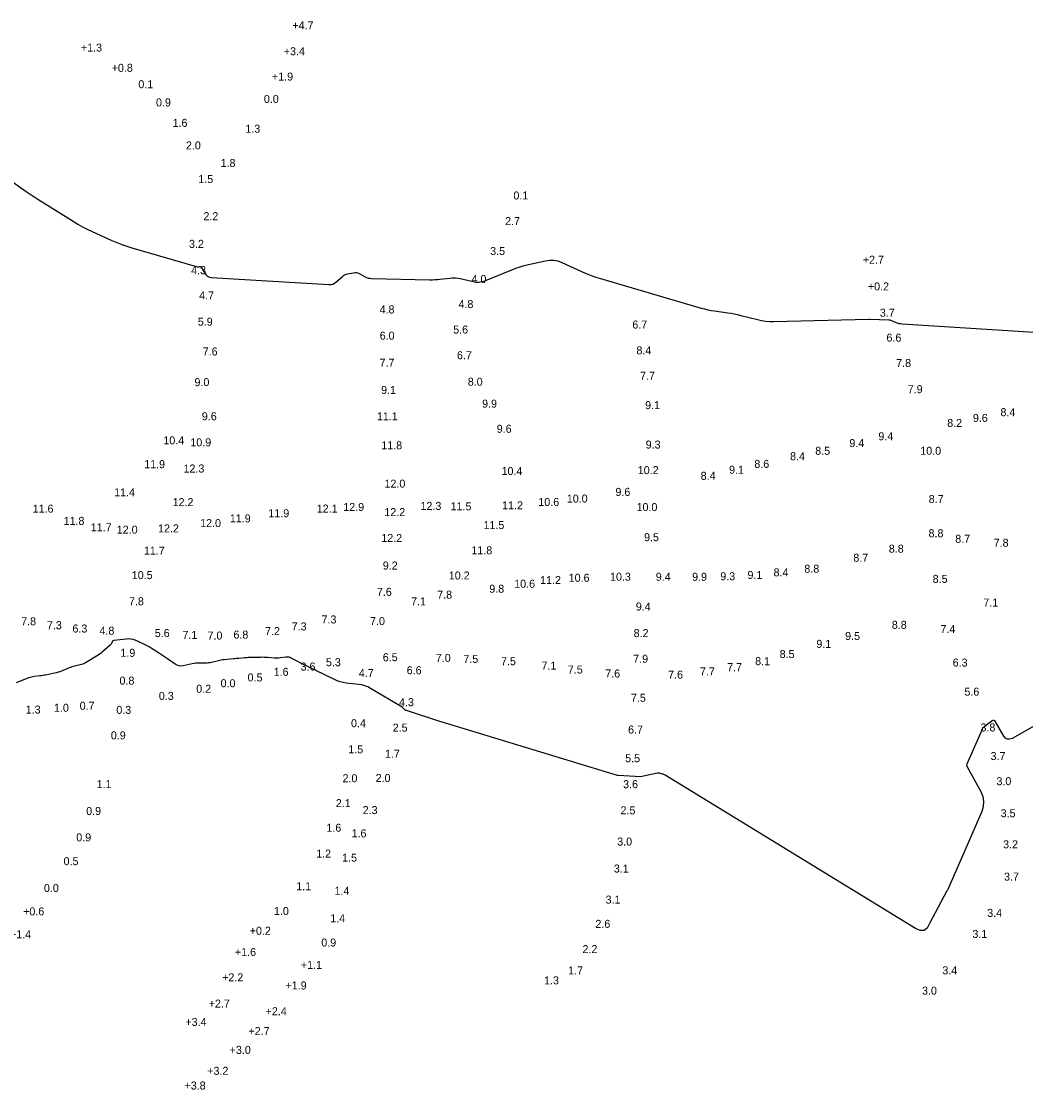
# Model space of a CAD drawing. Extents: x 837127 to 848654, y 3074248 to 3079868.
# Drawn here: x 846091.6 to 846483.6, y 3078129.4 to 3078546.3 of the extents above; entities that cross this region are included whole.
import ezdxf

# ---------------------------------------------------------------- set-up
doc = ezdxf.new("R2010")
doc.units = 0
for name, color, linetype in [('V-HYDS-MAJR', 7, 'Continuous'), ('V-HYDS-SOUN', 7, 'Continuous'), ('V-HYDS-SOUN-EXSS', 7, 'Continuous')]:
    doc.layers.add(name, color=color, linetype=linetype)

msp = doc.modelspace()

# ---------------------------------------------------------------- linework, layer by layer
at = {"layer": 'V-HYDS-MAJR'}
for points in [[(846087.17, 3078484.38), (846093.5, 3078479.9), (846094.61, 3078479.12), (846095.73, 3078478.36), (846096.87, 3078477.62), (846098.01, 3078476.89), (846111.79, 3078468.25), (846113.59, 3078467.17), (846115.42, 3078466.14), (846117.29, 3078465.18), (846119.19, 3078464.28), (846126.85, 3078460.82), (846128.78, 3078459.99), (846130.74, 3078459.22), (846132.72, 3078458.53), (846134.73, 3078457.91), (846160.32, 3078450.48), (846160.43, 3078450.46), (846160.55, 3078450.45), (846160.66, 3078450.45), (846160.77, 3078450.47), (846161.23, 3078450.57), (846161.34, 3078450.58), (846161.44, 3078450.56), (846161.52, 3078450.51), (846161.59, 3078450.43), (846163.63, 3078447.47), (846164.03, 3078447.01), (846164.49, 3078446.67), (846165.03, 3078446.45), (846165.63, 3078446.35), (846211.64, 3078443.58), (846212.39, 3078443.61), (846213.08, 3078443.77), (846213.73, 3078444.07), (846214.33, 3078444.5), (846216.91, 3078446.77), (846217.36, 3078447.12), (846217.85, 3078447.4), (846218.37, 3078447.61), (846218.93, 3078447.76), (846221.22, 3078448.2), (846221.78, 3078448.26), (846222.33, 3078448.22), (846222.87, 3078448.09), (846223.39, 3078447.87), (846225.76, 3078446.59), (846226.34, 3078446.33), (846226.93, 3078446.13), (846227.55, 3078446.01), (846228.18, 3078445.96), (846251.01, 3078445.47), (846252, 3078445.46), (846252.99, 3078445.49), (846253.98, 3078445.55), (846254.97, 3078445.65), (846258.93, 3078446.1), (846259.91, 3078446.17), (846260.9, 3078446.16), (846261.87, 3078446.06), (846262.85, 3078445.88), (846267.88, 3078444.72), (846269.04, 3078444.55), (846270.18, 3078444.55), (846271.31, 3078444.72), (846272.42, 3078445.08), (846283.02, 3078449.34), (846284.61, 3078449.95), (846286.22, 3078450.49), (846287.85, 3078450.96), (846289.5, 3078451.37), (846296.13, 3078452.89), (846297.78, 3078453.13), (846299.4, 3078453.1), (846300.98, 3078452.8), (846302.54, 3078452.22), (846310.26, 3078448.66), (846312.08, 3078447.87), (846313.92, 3078447.14), (846315.78, 3078446.48), (846317.68, 3078445.89), (846356.98, 3078434.4), (846358.24, 3078434.05), (846359.51, 3078433.75), (846360.8, 3078433.5), (846362.09, 3078433.3), (846367.28, 3078432.58), (846368.57, 3078432.38), (846369.86, 3078432.14), (846371.14, 3078431.87), (846372.41, 3078431.56), (846378.97, 3078429.88), (846380.49, 3078429.54), (846382.03, 3078429.31), (846383.57, 3078429.19), (846385.13, 3078429.17), (846422.36, 3078430.06), (846422.93, 3078430.03), (846430.22, 3078429.83), (846430.56, 3078429.75), (846433.09, 3078428.75), (846433.63, 3078428.56), (846434.19, 3078428.42), (846434.75, 3078428.32), (846435.32, 3078428.26), (846495.09, 3078424.46)], [(846542.85, 3078303.14), (846478.27, 3078266.46), (846477.31, 3078266.09), (846476.45, 3078266.11), (846475.71, 3078266.52), (846475.07, 3078267.33), (846471.69, 3078273.14), (846471.62, 3078273.24), (846471.53, 3078273.31), (846471.42, 3078273.35), (846471.3, 3078273.37), (846470.77, 3078273.37), (846470.65, 3078273.35), (846470.53, 3078273.32), (846470.43, 3078273.25), (846470.34, 3078273.17), (846466.6, 3078270.29), (846466.55, 3078270.15), (846466.57, 3078269.96), (846460.43, 3078256.18), (846460.76, 3078255.31), (846466.04, 3078245.71), (846466.85, 3078243.79), (846467.18, 3078241.84), (846467.04, 3078239.87), (846466.41, 3078237.88), (846453.23, 3078207.44), (846453.06, 3078207.16), (846452.83, 3078207), (846446, 3078194.25), (846445.14, 3078192.43), (846443.96, 3078191.49), (846442.45, 3078191.42), (846440.61, 3078192.21), (846342.82, 3078252.13), (846342.6, 3078252.26), (846342.37, 3078252.37), (846342.13, 3078252.46), (846341.88, 3078252.53), (846340.89, 3078252.8), (846340.64, 3078252.85), (846340.39, 3078252.87), (846340.14, 3078252.86), (846339.89, 3078252.82), (846334.44, 3078251.69), (846333.9, 3078251.56), (846333.39, 3078251.38), (846324.5, 3078251.98), (846324.35, 3078251.99), (846324.2, 3078252.02), (846255.41, 3078272.89), (846254.92, 3078273.08), (846241.87, 3078277.34), (846241.7, 3078277.37), (846241.54, 3078277.42), (846241.39, 3078277.5), (846241.25, 3078277.61), (846240.74, 3078278.12), (846240.6, 3078278.25), (846240.46, 3078278.36), (846240.32, 3078278.47), (846240.17, 3078278.57), (846227.83, 3078285.95), (846226.75, 3078286.52), (846225.64, 3078286.96), (846224.48, 3078287.29), (846223.29, 3078287.48), (846218.41, 3078288.03), (846217.21, 3078288.22), (846216.03, 3078288.51), (846214.89, 3078288.9), (846213.78, 3078289.39), (846206.49, 3078292.98), (846206.15, 3078293.15), (846205.82, 3078293.31), (846205.48, 3078293.47), (846205.14, 3078293.64), (846203.79, 3078294.28), (846203.45, 3078294.44), (846203.12, 3078294.61), (846202.78, 3078294.78), (846202.45, 3078294.95), (846196.94, 3078297.81), (846196.44, 3078298.03), (846195.92, 3078298.16), (846195.39, 3078298.2), (846194.85, 3078298.16), (846192.64, 3078297.84), (846192.09, 3078297.77), (846191.54, 3078297.74), (846190.98, 3078297.73), (846190.43, 3078297.77), (846187.66, 3078298), (846187.01, 3078298.05), (846186.36, 3078298.07), (846185.71, 3078298.09), (846185.06, 3078298.08), (846180.83, 3078297.98), (846180.28, 3078297.97), (846179.74, 3078297.94), (846179.2, 3078297.91), (846178.66, 3078297.86), (846176.5, 3078297.67), (846175.96, 3078297.62), (846175.42, 3078297.57), (846174.88, 3078297.53), (846174.34, 3078297.48), (846170.69, 3078297.15), (846170.13, 3078297.08), (846169.58, 3078297), (846169.03, 3078296.88), (846168.48, 3078296.75), (846166.31, 3078296.15), (846165.76, 3078296.02), (846165.21, 3078295.93), (846164.65, 3078295.87), (846164.09, 3078295.85), (846161.03, 3078295.84), (846160.34, 3078295.82), (846159.65, 3078295.77), (846158.96, 3078295.67), (846158.27, 3078295.55), (846154.68, 3078294.78), (846153.87, 3078294.69), (846153.09, 3078294.76), (846152.35, 3078294.99), (846151.64, 3078295.39), (846148.54, 3078297.54), (846147.79, 3078298.06), (846147.03, 3078298.57), (846146.28, 3078299.07), (846145.52, 3078299.57), (846142.23, 3078301.7), (846141.49, 3078302.16), (846140.73, 3078302.59), (846139.95, 3078302.98), (846139.16, 3078303.35), (846135.95, 3078304.74), (846135.14, 3078305.04), (846134.31, 3078305.21), (846133.47, 3078305.28), (846132.61, 3078305.22), (846127.65, 3078304.6), (846127.46, 3078304.56), (846127.3, 3078304.47), (846127.17, 3078304.34), (846127.07, 3078304.17), (846126.73, 3078303.42), (846126.63, 3078303.23), (846126.52, 3078303.07), (846126.39, 3078302.91), (846126.24, 3078302.77), (846123.23, 3078300.21), (846122.66, 3078299.75), (846122.08, 3078299.31), (846121.48, 3078298.9), (846120.86, 3078298.52), (846116.54, 3078295.95), (846116.05, 3078295.69), (846115.56, 3078295.46), (846115.04, 3078295.28), (846114.52, 3078295.13), (846112.37, 3078294.61), (846111.84, 3078294.47), (846111.31, 3078294.31), (846110.79, 3078294.13), (846110.28, 3078293.94), (846107.25, 3078292.72), (846106.58, 3078292.47), (846105.89, 3078292.25), (846105.19, 3078292.05), (846104.48, 3078291.89), (846101.01, 3078291.18), (846100.46, 3078291.07), (846099.91, 3078290.98), (846099.35, 3078290.9), (846098.8, 3078290.83), (846096.57, 3078290.58), (846096.02, 3078290.5), (846095.48, 3078290.38), (846094.94, 3078290.23), (846094.41, 3078290.05), (846089.56, 3078288.18)]]:
    msp.add_lwpolyline(points, dxfattribs=at)

# ---------------------------------------------------------------- texts
at = {"layer": 'V-HYDS-SOUN'}
for s, p in [('+4.7 ', (846197.33, 3078543.17)), ('+1.3 ', (846114.8, 3078534.49)), ('+3.4 ', (846193.99, 3078533.07)), ('+0.8 ', (846126.81, 3078526.6)), ('+1.9 ', (846189.38, 3078523.18)), ('0.1', (846137.22, 3078520.2)), (' 0.0', (846185.07, 3078514.47)), ('0.9', (846144.12, 3078513.1)), ('1.6', (846150.58, 3078505.11)), ('1.3', (846179, 3078502.84)), ('2.0', (846155.79, 3078496.31)), ('1.8', (846169.32, 3078489.46)), ('1.5', (846160.63, 3078483.19)), ('0.1', (846283.63, 3078476.78)), ('2.2', (846162.63, 3078468.7)), ('2.7', (846280.38, 3078466.77)), ('3.2', (846157, 3078457.9)), ('3.5', (846274.56, 3078455.1)), ('+2.7 ', (846420.02, 3078451.7)), ('4.3', (846157.85, 3078447.61)), ('4.0', (846267.28, 3078444.19)), ('+0.2 ', (846422, 3078441.28)), ('4.7', (846160.96, 3078437.76)), ('4.8', (846231.4, 3078432.29)), ('4.8', (846262.19, 3078434.38)), ('3.7', (846426.66, 3078431.03)), ('5.9', (846160.43, 3078427.53)), ('5.6', (846260.13, 3078424.45)), ('6.7', (846330.05, 3078426.39)), ('6.0', (846231.44, 3078422.07)), ('6.6', (846429.25, 3078421.3)), ('7.6', (846162.34, 3078415.89)), ('6.7', (846261.59, 3078414.42)), ('8.4', (846331.65, 3078416.33)), ('7.7', (846231.39, 3078411.53)), ('7.8', (846433.05, 3078411.39)), ('7.7', (846333.06, 3078406.4)), ('9.0', (846159.14, 3078403.92)), ('8.0', (846265.82, 3078404.09)), ('9.1', (846231.98, 3078400.88)), ('7.9', (846437.56, 3078401.18)), ('9.9', (846271.41, 3078395.52)), ('9.1', (846335.05, 3078394.96)), ('9.6', (846162.01, 3078390.6)), ('11.1 ', (846230.34, 3078390.61)), ('9.6', (846462.98, 3078389.95)), ('8.4', (846473.74, 3078392.2)), ('9.6', (846277.12, 3078385.72)), ('8.2', (846452.97, 3078388)), ('10.4 ', (846146.99, 3078381.21)), ('9.4', (846426.09, 3078382.8)), ('10.9 ', (846157.53, 3078380.43)), ('11.8 ', (846232.07, 3078379.26)), ('9.3', (846335.26, 3078379.56)), ('8.5', (846401.44, 3078377.13)), ('9.4', (846414.76, 3078380.14)), ('10.0 ', (846442.44, 3078377.13)), ('8.4', (846391.62, 3078375)), ('11.9 ', (846139.51, 3078371.91)), ('12.3 ', (846154.86, 3078370.21)), ('10.4 ', (846278.99, 3078369.24)), ('10.2 ', (846332.17, 3078369.59)), ('9.1', (846367.81, 3078369.73)), ('8.6', (846377.67, 3078372.02)), ('12.0 ', (846233.31, 3078364.31)), ('8.4', (846356.73, 3078367.36)), ('11.4 ', (846127.78, 3078360.94)), ('9.6', (846323.45, 3078361.1)), ('12.2 ', (846150.6, 3078357.08)), ('10.6 ', (846293.36, 3078357.15)), ('10.0 ', (846304.48, 3078358.48)), ('8.7', (846445.74, 3078358.29)), ('11.6 ', (846095.97, 3078354.55)), ('11.9 ', (846187.98, 3078352.75)), ('12.1 ', (846206.86, 3078354.57)), ('12.9 ', (846217.22, 3078355.19)), ('12.2 ', (846233.25, 3078353.2)), ('12.3 ', (846247.37, 3078355.62)), ('11.5 ', (846259.1, 3078355.44)), ('11.2 ', (846279.22, 3078355.83)), ('10.0 ', (846331.69, 3078355.16)), ('11.8 ', (846108.04, 3078349.77)), ('12.0 ', (846161.35, 3078348.93)), ('11.9 ', (846172.94, 3078350.76)), ('11.5 ', (846271.95, 3078348.14)), ('11.7 ', (846118.65, 3078347.27)), ('12.0 ', (846128.81, 3078346.35)), ('12.2 ', (846144.91, 3078346.84)), ('8.8', (846445.68, 3078344.95)), ('12.2 ', (846232.06, 3078343.11)), ('9.5', (846334.63, 3078343.41)), ('8.7', (846456.1, 3078342.78)), ('7.8', (846471.1, 3078341.24)), ('11.7 ', (846139.38, 3078338.14)), ('11.8 ', (846267.22, 3078338.29)), ('8.7', (846416.32, 3078335.38)), ('8.8', (846430.17, 3078338.92)), ('9.2', (846232.65, 3078332.35)), ('8.8', (846397.19, 3078331.1)), ('10.5 ', (846134.67, 3078328.61)), ('10.2 ', (846258.41, 3078328.47)), ('10.6 ', (846305.21, 3078327.57)), ('10.3 ', (846321.35, 3078327.98)), ('9.4', (846339.21, 3078327.97)), ('9.9', (846353.39, 3078327.95)), ('9.3', (846364.39, 3078328.16)), ('9.1', (846375, 3078328.68)), ('8.4', (846385.17, 3078329.68)), ('8.5', (846447.29, 3078327.14)), ('9.8', (846274.22, 3078323.29)), ('10.6 ', (846283.93, 3078325.23)), ('11.2 ', (846294.05, 3078326.69)), ('7.6', (846230.34, 3078322.07)), ('7.8', (846253.89, 3078320.97)), ('7.8', (846133.57, 3078318.4)), ('7.1', (846243.7, 3078318.35)), ('9.4', (846331.42, 3078316.35)), ('7.1', (846467.07, 3078317.87)), ('7.8', (846091.49, 3078310.59)), ('7.3', (846208.73, 3078311.31)), ('7.0', (846227.68, 3078310.68)), ('6.3', (846111.5, 3078307.77)), ('4.8', (846122.05, 3078306.94)), ('5.6', (846143.63, 3078305.98)), ('7.2', (846186.68, 3078306.74)), ('7.3', (846197.09, 3078308.58)), ('8.2', (846330.57, 3078305.97)), ('8.8', (846431.34, 3078309.2)), ('7.4', (846450.32, 3078307.55)), ('7.1', (846154.47, 3078305.29)), ('7.0', (846164.24, 3078305.02)), ('6.8', (846174.34, 3078305.39)), ('9.1', (846401.87, 3078301.78)), ('9.5', (846413.12, 3078304.85)), ('1.9', (846130.21, 3078298.28)), ('8.5', (846387.56, 3078297.82)), ('5.3', (846210.45, 3078294.62)), ('6.5', (846232.64, 3078296.55)), ('7.0', (846253.35, 3078296.29)), ('7.5', (846264.1, 3078295.9)), ('7.5', (846278.79, 3078295)), ('7.9', (846330.39, 3078295.96)), ('8.1', (846378, 3078295.02)), ('6.3', (846455.1, 3078294.47)), ('1.6', (846190.06, 3078290.87)), ('3.6', (846200.56, 3078292.91)), ('4.7', (846223.29, 3078290.4)), ('6.6', (846241.97, 3078291.47)), ('7.1', (846294.6, 3078293.31)), ('7.5', (846304.87, 3078291.76)), ('7.6', (846319.47, 3078290.21)), ('7.6', (846344.01, 3078289.76)), ('7.7', (846356.44, 3078291.02)), ('7.7', (846367.06, 3078292.68)), ('0.8', (846129.87, 3078287.43)), (' 0.0', (846168.17, 3078286.41)), ('0.5', (846179.87, 3078288.67)), ('0.3', (846145.23, 3078281.47)), ('0.2', (846159.83, 3078284.25)), ('5.6', (846459.67, 3078283.12)), ('1.0', (846104.29, 3078276.84)), ('0.7', (846114.32, 3078277.62)), ('4.3', (846238.99, 3078279.01)), ('7.5', (846329.5, 3078280.74)), ('0.3', (846128.63, 3078276.01)), ('0.4', (846220.23, 3078270.81)), ('2.5', (846236.51, 3078269.09)), ('3.8', (846465.95, 3078269.15)), ('0.9', (846126.5, 3078266.06)), ('6.7', (846328.39, 3078268.33)), ('1.5', (846219.17, 3078260.62)), ('1.7', (846233.47, 3078258.87)), ('5.5', (846327.27, 3078257.14)), ('3.7', (846469.89, 3078257.98)), ('2.0', (846216.93, 3078249.33)), ('2.0', (846229.86, 3078249.42)), ('3.0', (846472.18, 3078248.16)), ('1.1', (846120.92, 3078247.02)), ('3.6', (846326.46, 3078247.01)), ('2.1', (846214.3, 3078239.61)), ('0.9', (846116.86, 3078236.56)), ('2.3', (846224.8, 3078236.89)), ('2.5', (846325.44, 3078236.81)), ('3.5', (846473.82, 3078235.67)), ('1.6', (846210.63, 3078230)), ('1.6', (846220.46, 3078227.82)), ('0.9', (846113, 3078226.26)), ('3.0', (846324.15, 3078224.62)), ('3.2', (846474.78, 3078223.54)), ('1.2', (846206.65, 3078219.92)), ('0.5', (846108.04, 3078216.96)), ('1.5', (846216.77, 3078218.34)), ('3.1', (846322.84, 3078214.09)), ('3.7', (846475.14, 3078210.93)), (' 0.0', (846099.19, 3078206.51)), ('1.1', (846198.85, 3078207.18)), ('1.4', (846213.79, 3078205.4)), ('3.1', (846319.61, 3078201.96)), ('+0.6 ', (846092.25, 3078197.36)), ('1.0', (846190.17, 3078197.51)), ('1.4', (846212.13, 3078194.71)), ('3.4', (846468.58, 3078196.77)), ('+0.2 ', (846180.7, 3078189.8)), ('2.6', (846315.63, 3078192.5)), ('+1.4 ', (846087.12, 3078188.41)), ('0.9', (846208.63, 3078185.21)), ('3.1', (846462.79, 3078188.56)), ('+1.6 ', (846174.92, 3078181.49)), ('2.2', (846310.6, 3078182.65)), ('+1.1 ', (846200.68, 3078176.48)), ('1.7', (846304.99, 3078174.32)), ('3.4', (846451.05, 3078174.35)), ('+2.2 ', (846169.93, 3078171.62)), ('+1.9 ', (846194.66, 3078168.45)), ('1.3', (846295.6, 3078170.43)), ('3.0', (846443.12, 3078166.43)), ('+2.7 ', (846164.68, 3078161.37)), ('+2.4 ', (846186.91, 3078158.39)), ('+3.4 ', (846155.58, 3078154.22)), ('+2.7 ', (846180.2, 3078150.65)), ('+3.0 ', (846172.86, 3078143.3)), ('+3.2 ', (846164.12, 3078135.14)), ('+3.8 ', (846155.25, 3078129.4))]:
    msp.add_text(s, height=3.125, dxfattribs=at).set_placement(p)
at = {"layer": 'V-HYDS-SOUN-EXSS'}
for s, p in [('7.3', (846101.53, 3078309.06)), ('1.3', (846093.26, 3078276.14))]:
    msp.add_text(s, height=3.125, dxfattribs=at).set_placement(p)

doc.saveas('drawing.dxf')
